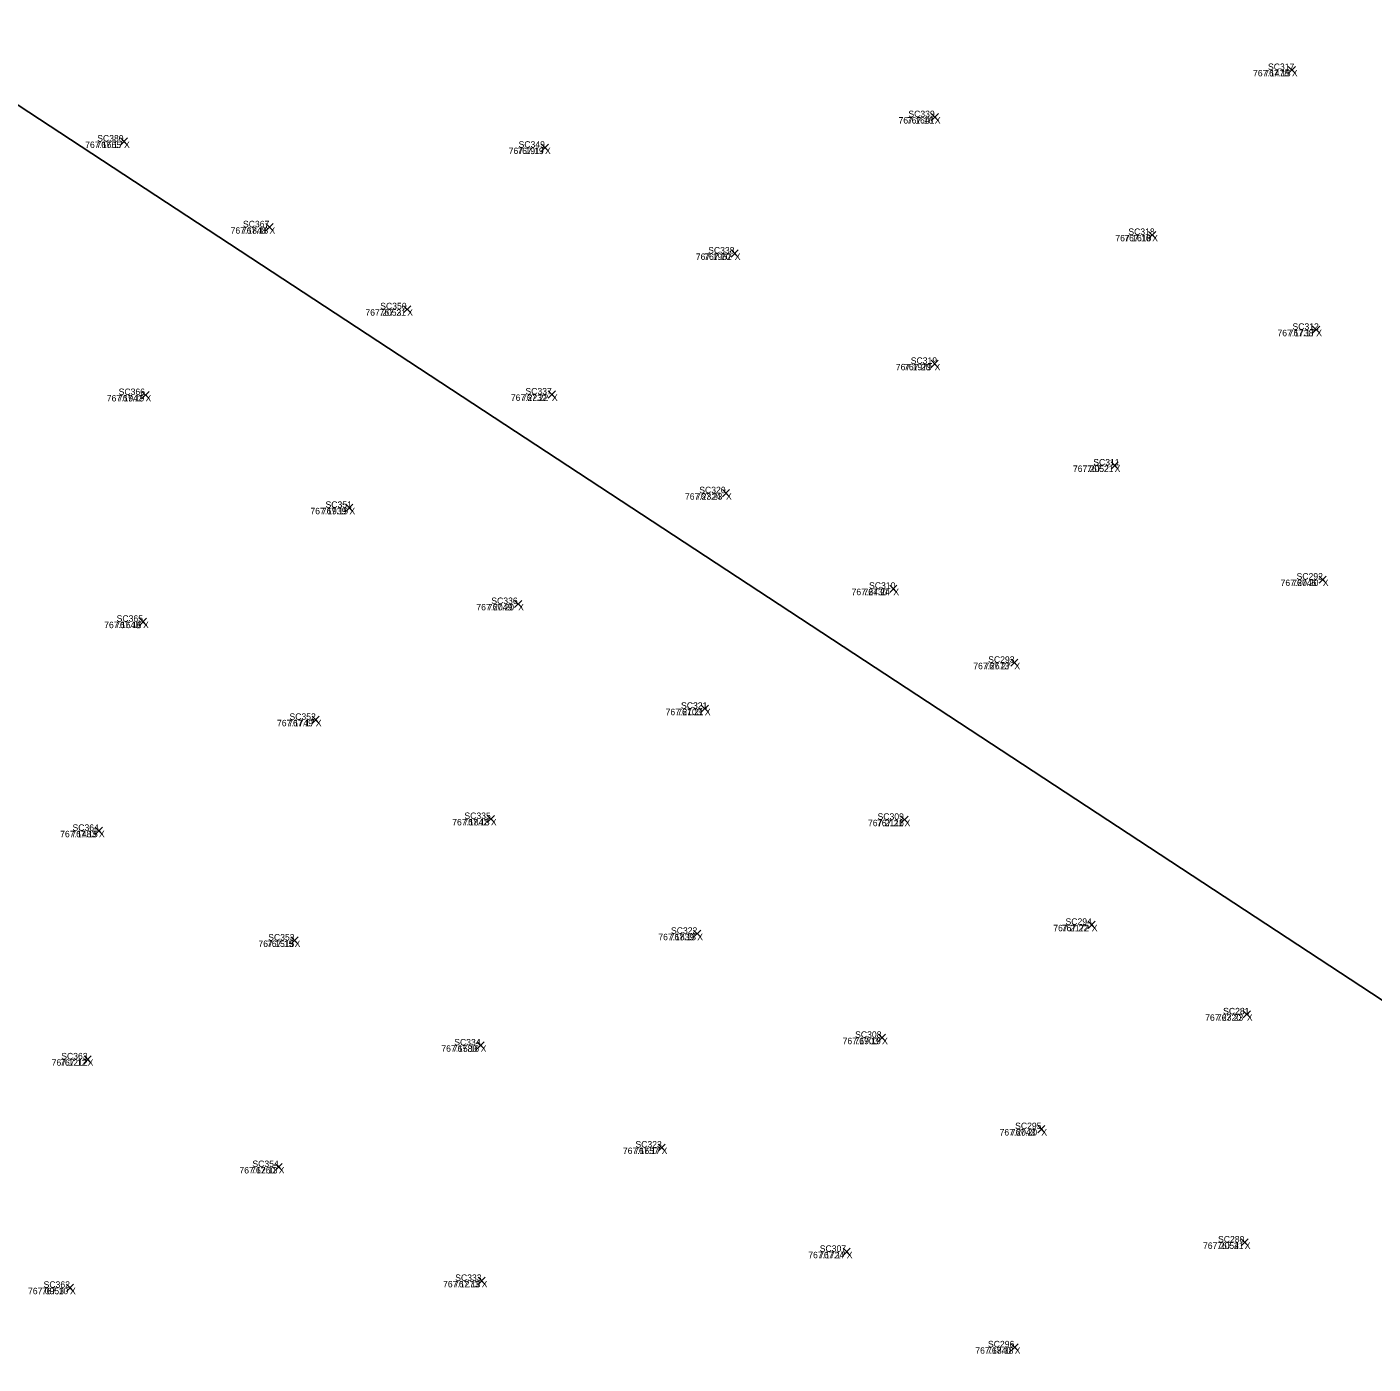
# Model space of a CAD drawing. Extents: x 1845019 to 1877956, y 680444 to 701081.
# Drawn here: x 1857650.03 to 1857662.57, y 694277.17 to 694289.61 of the extents above; entities that cross this region are included whole.
import ezdxf

# ---------------------------------------------------------------- set-up
doc = ezdxf.new("R2010")
doc.units = 0
for name, color, linetype in [('SV_X_CL_Survey_20', 7, 'Continuous'), ('SV_X_Random_Point', 7, 'Continuous'), ('SV_X_Text_Comment', 7, 'Continuous'), ('SV_X_Text_Elevation', 7, 'Continuous'), ('SV_X_Text_Name', 7, 'Continuous')]:
    doc.layers.add(name, color=color, linetype=linetype)

msp = doc.modelspace()

# ---------------------------------------------------------------- linework, layer by layer
at = {"layer": 'SV_X_CL_Survey_20'}
msp.add_line((1856038.267, 695346.314), (1858797.327, 693536.085), dxfattribs=at)
at = {"layer": 'SV_X_Random_Point'}
for p, q in [((1857661.777, 694289.176), (1857661.844, 694289.242)), ((1857661.777, 694289.242), (1857661.844, 694289.176)), ((1857661.777, 694289.176), (1857661.844, 694289.242)), ((1857661.777, 694289.242), (1857661.844, 694289.176)), ((1857658.454, 694288.736), (1857658.521, 694288.803)), ((1857658.454, 694288.803), (1857658.521, 694288.736)), ((1857658.454, 694288.736), (1857658.521, 694288.803)), ((1857658.454, 694288.803), (1857658.521, 694288.736)), ((1857650.906, 694288.51), (1857650.972, 694288.576)), ((1857650.906, 694288.576), (1857650.972, 694288.51)), ((1857650.906, 694288.51), (1857650.972, 694288.576)), ((1857650.906, 694288.576), (1857650.972, 694288.51)), ((1857654.825, 694288.452), (1857654.891, 694288.519)), ((1857654.825, 694288.519), (1857654.891, 694288.452)), ((1857654.825, 694288.452), (1857654.891, 694288.519)), ((1857654.825, 694288.519), (1857654.891, 694288.452)), ((1857652.259, 694287.712), (1857652.326, 694287.779)), ((1857652.259, 694287.779), (1857652.326, 694287.712)), ((1857652.259, 694287.712), (1857652.326, 694287.779)), ((1857652.259, 694287.779), (1857652.326, 694287.712)), ((1857660.478, 694287.64), (1857660.545, 694287.707)), ((1857660.478, 694287.707), (1857660.545, 694287.64)), ((1857660.478, 694287.64), (1857660.545, 694287.707)), ((1857660.478, 694287.707), (1857660.545, 694287.64)), ((1857656.591, 694287.468), (1857656.657, 694287.534)), ((1857656.591, 694287.534), (1857656.657, 694287.468)), ((1857656.591, 694287.468), (1857656.657, 694287.534)), ((1857656.591, 694287.534), (1857656.657, 694287.468)), ((1857653.541, 694286.948), (1857653.608, 694287.015)), ((1857653.541, 694287.015), (1857653.608, 694286.948)), ((1857653.541, 694286.948), (1857653.608, 694287.015)), ((1857653.541, 694287.015), (1857653.608, 694286.948)), ((1857662.004, 694286.758), (1857662.071, 694286.825)), ((1857662.004, 694286.825), (1857662.071, 694286.758)), ((1857662.004, 694286.758), (1857662.071, 694286.825)), ((1857662.004, 694286.825), (1857662.071, 694286.758)), ((1857658.452, 694286.44), (1857658.518, 694286.507)), ((1857658.452, 694286.507), (1857658.518, 694286.44)), ((1857658.452, 694286.44), (1857658.518, 694286.507)), ((1857658.452, 694286.507), (1857658.518, 694286.44)), ((1857651.106, 694286.151), (1857651.173, 694286.218)), ((1857651.106, 694286.218), (1857651.173, 694286.151)), ((1857651.106, 694286.151), (1857651.173, 694286.218)), ((1857651.106, 694286.218), (1857651.173, 694286.151)), ((1857654.889, 694286.155), (1857654.956, 694286.222)), ((1857654.889, 694286.222), (1857654.956, 694286.155)), ((1857654.889, 694286.155), (1857654.956, 694286.222)), ((1857654.889, 694286.222), (1857654.956, 694286.155)), ((1857660.128, 694285.495), (1857660.195, 694285.562)), ((1857660.128, 694285.562), (1857660.195, 694285.495)), ((1857660.128, 694285.495), (1857660.195, 694285.562)), ((1857660.128, 694285.562), (1857660.195, 694285.495)), ((1857656.51, 694285.237), (1857656.577, 694285.303)), ((1857656.51, 694285.303), (1857656.577, 694285.237)), ((1857656.51, 694285.237), (1857656.577, 694285.303)), ((1857656.51, 694285.303), (1857656.577, 694285.237)), ((1857653.004, 694285.1), (1857653.07, 694285.167)), ((1857653.004, 694285.167), (1857653.07, 694285.1)), ((1857653.004, 694285.1), (1857653.07, 694285.167)), ((1857653.004, 694285.167), (1857653.07, 694285.1)), ((1857658.068, 694284.347), (1857658.135, 694284.414)), ((1857658.068, 694284.414), (1857658.135, 694284.347)), ((1857658.068, 694284.347), (1857658.135, 694284.414)), ((1857658.068, 694284.414), (1857658.135, 694284.347)), ((1857662.065, 694284.432), (1857662.132, 694284.499)), ((1857662.065, 694284.499), (1857662.132, 694284.432)), ((1857662.065, 694284.432), (1857662.132, 694284.499)), ((1857662.065, 694284.499), (1857662.132, 694284.432)), ((1857654.575, 694284.205), (1857654.642, 694284.272)), ((1857654.575, 694284.272), (1857654.642, 694284.205)), ((1857654.575, 694284.205), (1857654.642, 694284.272)), ((1857654.575, 694284.272), (1857654.642, 694284.205)), ((1857651.083, 694284.04), (1857651.149, 694284.107)), ((1857651.083, 694284.107), (1857651.149, 694284.04)), ((1857651.083, 694284.04), (1857651.149, 694284.107)), ((1857651.083, 694284.107), (1857651.149, 694284.04)), ((1857659.195, 694283.659), (1857659.261, 694283.726)), ((1857659.195, 694283.726), (1857659.261, 694283.659)), ((1857659.195, 694283.659), (1857659.261, 694283.726)), ((1857659.195, 694283.726), (1857659.261, 694283.659)), ((1857656.312, 694283.231), (1857656.379, 694283.298)), ((1857656.312, 694283.298), (1857656.379, 694283.231)), ((1857656.312, 694283.231), (1857656.379, 694283.298)), ((1857656.312, 694283.298), (1857656.379, 694283.231)), ((1857652.69, 694283.128), (1857652.757, 694283.195)), ((1857652.69, 694283.195), (1857652.757, 694283.128)), ((1857652.69, 694283.128), (1857652.757, 694283.195)), ((1857652.69, 694283.195), (1857652.757, 694283.128)), ((1857654.321, 694282.205), (1857654.387, 694282.271)), ((1857654.321, 694282.271), (1857654.387, 694282.205)), ((1857654.321, 694282.205), (1857654.387, 694282.271)), ((1857654.321, 694282.271), (1857654.387, 694282.205)), ((1857658.172, 694282.198), (1857658.238, 694282.264)), ((1857658.172, 694282.264), (1857658.238, 694282.198)), ((1857658.172, 694282.198), (1857658.238, 694282.264)), ((1857658.172, 694282.264), (1857658.238, 694282.198)), ((1857650.671, 694282.095), (1857650.738, 694282.161)), ((1857650.671, 694282.161), (1857650.738, 694282.095)), ((1857650.671, 694282.095), (1857650.738, 694282.161)), ((1857650.671, 694282.161), (1857650.738, 694282.095)), ((1857659.915, 694281.22), (1857659.981, 694281.287)), ((1857659.915, 694281.287), (1857659.981, 694281.22)), ((1857659.915, 694281.22), (1857659.981, 694281.287)), ((1857659.915, 694281.287), (1857659.981, 694281.22)), ((1857652.493, 694281.074), (1857652.56, 694281.14)), ((1857652.493, 694281.14), (1857652.56, 694281.074)), ((1857652.493, 694281.074), (1857652.56, 694281.14)), ((1857652.493, 694281.14), (1857652.56, 694281.074)), ((1857656.241, 694281.137), (1857656.308, 694281.204)), ((1857656.241, 694281.204), (1857656.308, 694281.137)), ((1857656.241, 694281.137), (1857656.308, 694281.204)), ((1857656.241, 694281.204), (1857656.308, 694281.137)), ((1857661.359, 694280.387), (1857661.425, 694280.453)), ((1857661.359, 694280.453), (1857661.425, 694280.387)), ((1857661.359, 694280.387), (1857661.425, 694280.453)), ((1857661.359, 694280.453), (1857661.425, 694280.387)), ((1857654.226, 694280.098), (1857654.292, 694280.165)), ((1857654.226, 694280.165), (1857654.292, 694280.098)), ((1857654.226, 694280.098), (1857654.292, 694280.165)), ((1857654.226, 694280.165), (1857654.292, 694280.098)), ((1857657.963, 694280.169), (1857658.029, 694280.235)), ((1857657.963, 694280.235), (1857658.029, 694280.169)), ((1857657.963, 694280.169), (1857658.029, 694280.235)), ((1857657.963, 694280.235), (1857658.029, 694280.169)), ((1857650.567, 694279.967), (1857650.633, 694280.034)), ((1857650.567, 694280.034), (1857650.633, 694279.967)), ((1857650.567, 694279.967), (1857650.633, 694280.034)), ((1857650.567, 694280.034), (1857650.633, 694279.967)), ((1857659.445, 694279.318), (1857659.512, 694279.385)), ((1857659.445, 694279.385), (1857659.512, 694279.318)), ((1857659.445, 694279.318), (1857659.512, 694279.385)), ((1857659.445, 694279.385), (1857659.512, 694279.318)), ((1857655.911, 694279.147), (1857655.978, 694279.213)), ((1857655.911, 694279.213), (1857655.978, 694279.147)), ((1857655.911, 694279.147), (1857655.978, 694279.213)), ((1857655.911, 694279.213), (1857655.978, 694279.147)), ((1857652.345, 694278.966), (1857652.412, 694279.033)), ((1857652.345, 694279.033), (1857652.412, 694278.966)), ((1857652.345, 694278.966), (1857652.412, 694279.033)), ((1857652.345, 694279.033), (1857652.412, 694278.966)), ((1857657.633, 694278.176), (1857657.7, 694278.243)), ((1857657.633, 694278.243), (1857657.7, 694278.176)), ((1857657.633, 694278.176), (1857657.7, 694278.243)), ((1857657.633, 694278.243), (1857657.7, 694278.176)), ((1857661.339, 694278.264), (1857661.406, 694278.331)), ((1857661.339, 694278.331), (1857661.406, 694278.264)), ((1857661.339, 694278.264), (1857661.406, 694278.331)), ((1857661.339, 694278.331), (1857661.406, 694278.264)), ((1857650.402, 694277.841), (1857650.469, 694277.908)), ((1857650.402, 694277.908), (1857650.469, 694277.841)), ((1857650.402, 694277.841), (1857650.469, 694277.908)), ((1857650.402, 694277.908), (1857650.469, 694277.841)), ((1857654.235, 694277.906), (1857654.301, 694277.973)), ((1857654.235, 694277.973), (1857654.301, 694277.906)), ((1857654.235, 694277.906), (1857654.301, 694277.973)), ((1857654.235, 694277.973), (1857654.301, 694277.906)), ((1857659.197, 694277.287), (1857659.264, 694277.354)), ((1857659.197, 694277.354), (1857659.264, 694277.287)), ((1857659.197, 694277.287), (1857659.264, 694277.354)), ((1857659.197, 694277.354), (1857659.264, 694277.287))]:
    msp.add_line(p, q, dxfattribs=at)

# ---------------------------------------------------------------- texts
at = {"layer": 'SV_X_Text_Comment'}
for p in [(1857661.811, 694289.149), (1857658.487, 694288.71), (1857650.939, 694288.483), (1857654.858, 694288.426), (1857652.293, 694287.685), (1857660.511, 694287.614), (1857656.624, 694287.441), (1857653.575, 694286.922), (1857662.038, 694286.731), (1857658.485, 694286.414), (1857651.139, 694286.124), (1857654.922, 694286.129), (1857660.161, 694285.468), (1857656.543, 694285.21), (1857653.037, 694285.074), (1857658.101, 694284.321), (1857662.099, 694284.406), (1857654.608, 694284.179), (1857651.116, 694284.014), (1857659.228, 694283.632), (1857656.346, 694283.204), (1857652.724, 694283.101), (1857650.705, 694282.068), (1857654.354, 694282.178), (1857658.205, 694282.171), (1857659.948, 694281.193), (1857656.275, 694281.11), (1857652.527, 694281.047), (1857661.392, 694280.36), (1857654.259, 694280.071), (1857657.996, 694280.142), (1857650.6, 694279.941), (1857659.479, 694279.292), (1857655.944, 694279.12), (1857652.379, 694278.939), (1857661.372, 694278.237), (1857657.667, 694278.15), (1857650.436, 694277.815), (1857654.268, 694277.879), (1857659.231, 694277.261)]:
    msp.add_text('X', height=0.06, dxfattribs=at).set_placement(p)
at = {"layer": 'SV_X_Text_Elevation'}
for s, p in [('767.1478', (1857661.45, 694289.149)), ('767.15', (1857661.554, 694289.149)), ('767.1641', (1857658.149, 694288.71)), ('767.16', (1857658.227, 694288.71)), ('767.1665', (1857650.577, 694288.483)), ('767.17', (1857650.682, 694288.483)), ('767.1917', (1857654.52, 694288.426)), ('767.19', (1857654.601, 694288.426)), ('767.1848', (1857651.931, 694287.685)), ('767.18', (1857652.036, 694287.685)), ('767.1610', (1857660.168, 694287.614)), ('767.16', (1857660.251, 694287.614)), ('767.1962', (1857656.262, 694287.441)), ('767.20', (1857656.34, 694287.441)), ('767.2053', (1857653.186, 694286.922)), ('767.21', (1857653.318, 694286.922)), ('767.1738', (1857661.677, 694286.731)), ('767.17', (1857661.781, 694286.731)), ('767.1979', (1857658.124, 694286.414)), ('767.20', (1857658.201, 694286.414)), ('767.1942', (1857650.778, 694286.124)), ('767.19', (1857650.882, 694286.124)), ('767.2232', (1857654.54, 694286.129)), ('767.22', (1857654.644, 694286.129)), ('767.2052', (1857659.773, 694285.468)), ('767.21', (1857659.905, 694285.468)), ('767.2324', (1857656.161, 694285.21)), ('767.23', (1857656.264, 694285.21)), ('767.1939', (1857652.674, 694285.074)), ('767.19', (1857652.78, 694285.074)), ('767.2430', (1857657.712, 694284.321)), ('767.24', (1857657.823, 694284.321)), ('767.2046', (1857661.706, 694284.406)), ('767.20', (1857661.814, 694284.406)), ('767.2049', (1857654.219, 694284.179)), ('767.20', (1857654.324, 694284.179)), ('767.1648', (1857650.754, 694284.014)), ('767.16', (1857650.856, 694284.014)), ('767.2673', (1857658.845, 694283.632)), ('767.27', (1857658.949, 694283.632)), ('767.2103', (1857655.981, 694283.204)), ('767.21', (1857656.089, 694283.204)), ('767.1749', (1857652.363, 694283.101)), ('767.17', (1857652.467, 694283.101)), ('767.1483', (1857650.344, 694282.068)), ('767.15', (1857650.448, 694282.068)), ('767.1842', (1857653.994, 694282.178)), ('767.18', (1857654.097, 694282.178)), ('767.2116', (1857657.865, 694282.171)), ('767.21', (1857657.948, 694282.171)), ('767.2172', (1857659.59, 694281.193)), ('767.22', (1857659.669, 694281.193)), ('767.1839', (1857655.913, 694281.11)), ('767.18', (1857656.018, 694281.11)), ('767.1515', (1857652.19, 694281.047)), ('767.15', (1857652.27, 694281.047)), ('767.2320', (1857661.004, 694280.36)), ('767.23', (1857661.113, 694280.36)), ('767.1580', (1857653.893, 694280.071)), ('767.16', (1857653.999, 694280.071)), ('767.1903', (1857657.629, 694280.142)), ('767.19', (1857657.739, 694280.142)), ('767.1212', (1857650.265, 694279.941)), ('767.12', (1857650.344, 694279.941)), ('767.2043', (1857659.09, 694279.292)), ('767.20', (1857659.194, 694279.292)), ('767.1657', (1857655.583, 694279.12)), ('767.17', (1857655.688, 694279.12)), ('767.1260', (1857652.013, 694278.939)), ('767.13', (1857652.122, 694278.939)), ('767.2054', (1857660.984, 694278.237)), ('767.21', (1857661.116, 694278.237)), ('767.1724', (1857657.309, 694278.15)), ('767.17', (1857657.41, 694278.15)), ('767.0953', (1857650.045, 694277.815)), ('767.10', (1857650.174, 694277.815)), ('767.1273', (1857653.909, 694277.879)), ('767.13', (1857654.011, 694277.879)), ('767.1840', (1857658.864, 694277.261)), ('767.18', (1857658.974, 694277.261))]:
    msp.add_text(s, height=0.06, dxfattribs=at).set_placement(p)
at = {"layer": 'SV_X_Text_Name'}
for s, p in [('SC317', (1857661.589, 694289.209)), ('SC317', (1857661.589, 694289.209)), ('SC339', (1857658.241, 694288.77)), ('SC339', (1857658.241, 694288.77)), ('SC380', (1857650.689, 694288.543)), ('SC380', (1857650.689, 694288.543)), ('SC349', (1857654.612, 694288.486)), ('SC349', (1857654.612, 694288.486)), ('SC367', (1857652.046, 694287.745)), ('SC367', (1857652.046, 694287.745)), ('SC318', (1857660.289, 694287.674)), ('SC318', (1857660.289, 694287.674)), ('SC338', (1857656.377, 694287.501)), ('SC338', (1857656.377, 694287.501)), ('SC350', (1857653.324, 694286.982)), ('SC350', (1857653.324, 694286.982)), ('SC312', (1857661.817, 694286.791)), ('SC312', (1857661.817, 694286.791)), ('SC319', (1857658.263, 694286.474)), ('SC319', (1857658.263, 694286.474)), ('SC366', (1857650.889, 694286.184)), ('SC366', (1857650.889, 694286.184)), ('SC337', (1857654.676, 694286.189)), ('SC337', (1857654.676, 694286.189)), ('SC311', (1857659.962, 694285.528)), ('SC311', (1857659.963, 694285.528)), ('SC320', (1857656.294, 694285.27)), ('SC320', (1857656.294, 694285.27)), ('SC351', (1857652.814, 694285.134)), ('SC351', (1857652.815, 694285.134)), ('SC292', (1857661.855, 694284.466)), ('SC292', (1857661.855, 694284.466)), ('SC310', (1857657.875, 694284.381)), ('SC310', (1857657.875, 694284.381)), ('SC336', (1857654.358, 694284.239)), ('SC336', (1857654.358, 694284.239)), ('SC365', (1857650.87, 694284.074)), ('SC365', (1857650.87, 694284.074)), ('SC293', (1857658.984, 694283.692)), ('SC293', (1857658.984, 694283.692)), ('SC321', (1857656.124, 694283.264)), ('SC321', (1857656.125, 694283.264)), ('SC352', (1857652.479, 694283.161)), ('SC352', (1857652.479, 694283.161)), ('SC335', (1857654.108, 694282.238)), ('SC335', (1857654.108, 694282.238)), ('SC309', (1857657.954, 694282.231)), ('SC309', (1857657.954, 694282.231)), ('SC364', (1857650.459, 694282.128)), ('SC364', (1857650.459, 694282.128)), ('SC294', (1857659.704, 694281.253)), ('SC294', (1857659.704, 694281.253)), ('SC353', (1857652.281, 694281.107)), ('SC353', (1857652.281, 694281.107)), ('SC322', (1857656.031, 694281.17)), ('SC322', (1857656.031, 694281.17)), ('SC281', (1857661.171, 694280.42)), ('SC281', (1857661.172, 694280.42)), ('SC308', (1857657.745, 694280.202)), ('SC308', (1857657.745, 694280.202)), ('SC334', (1857654.013, 694280.131)), ('SC334', (1857654.013, 694280.131)), ('SC363', (1857650.354, 694280.001)), ('SC363', (1857650.354, 694280.001)), ('SC295', (1857659.235, 694279.352)), ('SC295', (1857659.235, 694279.352)), ('SC323', (1857655.7, 694279.18)), ('SC323', (1857655.7, 694279.18)), ('SC354', (1857652.134, 694278.999)), ('SC354', (1857652.134, 694278.999)), ('SC307', (1857657.416, 694278.21)), ('SC307', (1857657.416, 694278.21)), ('SC280', (1857661.124, 694278.297)), ('SC280', (1857661.124, 694278.297)), ('SC333', (1857654.022, 694277.939)), ('SC333', (1857654.022, 694277.939)), ('SC362', (1857650.19, 694277.875)), ('SC362', (1857650.19, 694277.875)), ('SC296', (1857658.982, 694277.321)), ('SC296', (1857658.982, 694277.321))]:
    msp.add_text(s, height=0.06, dxfattribs=at).set_placement(p)

doc.saveas('drawing.dxf')
